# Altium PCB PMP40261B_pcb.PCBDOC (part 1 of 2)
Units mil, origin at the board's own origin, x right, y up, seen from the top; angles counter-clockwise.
Board outline 16142.73 x 9056.12 mil, 2 copper layers (TOP, BOTTOM), stack 10.4 mil thick; 242 components, 121 nets, 575 pads, 103 vias.
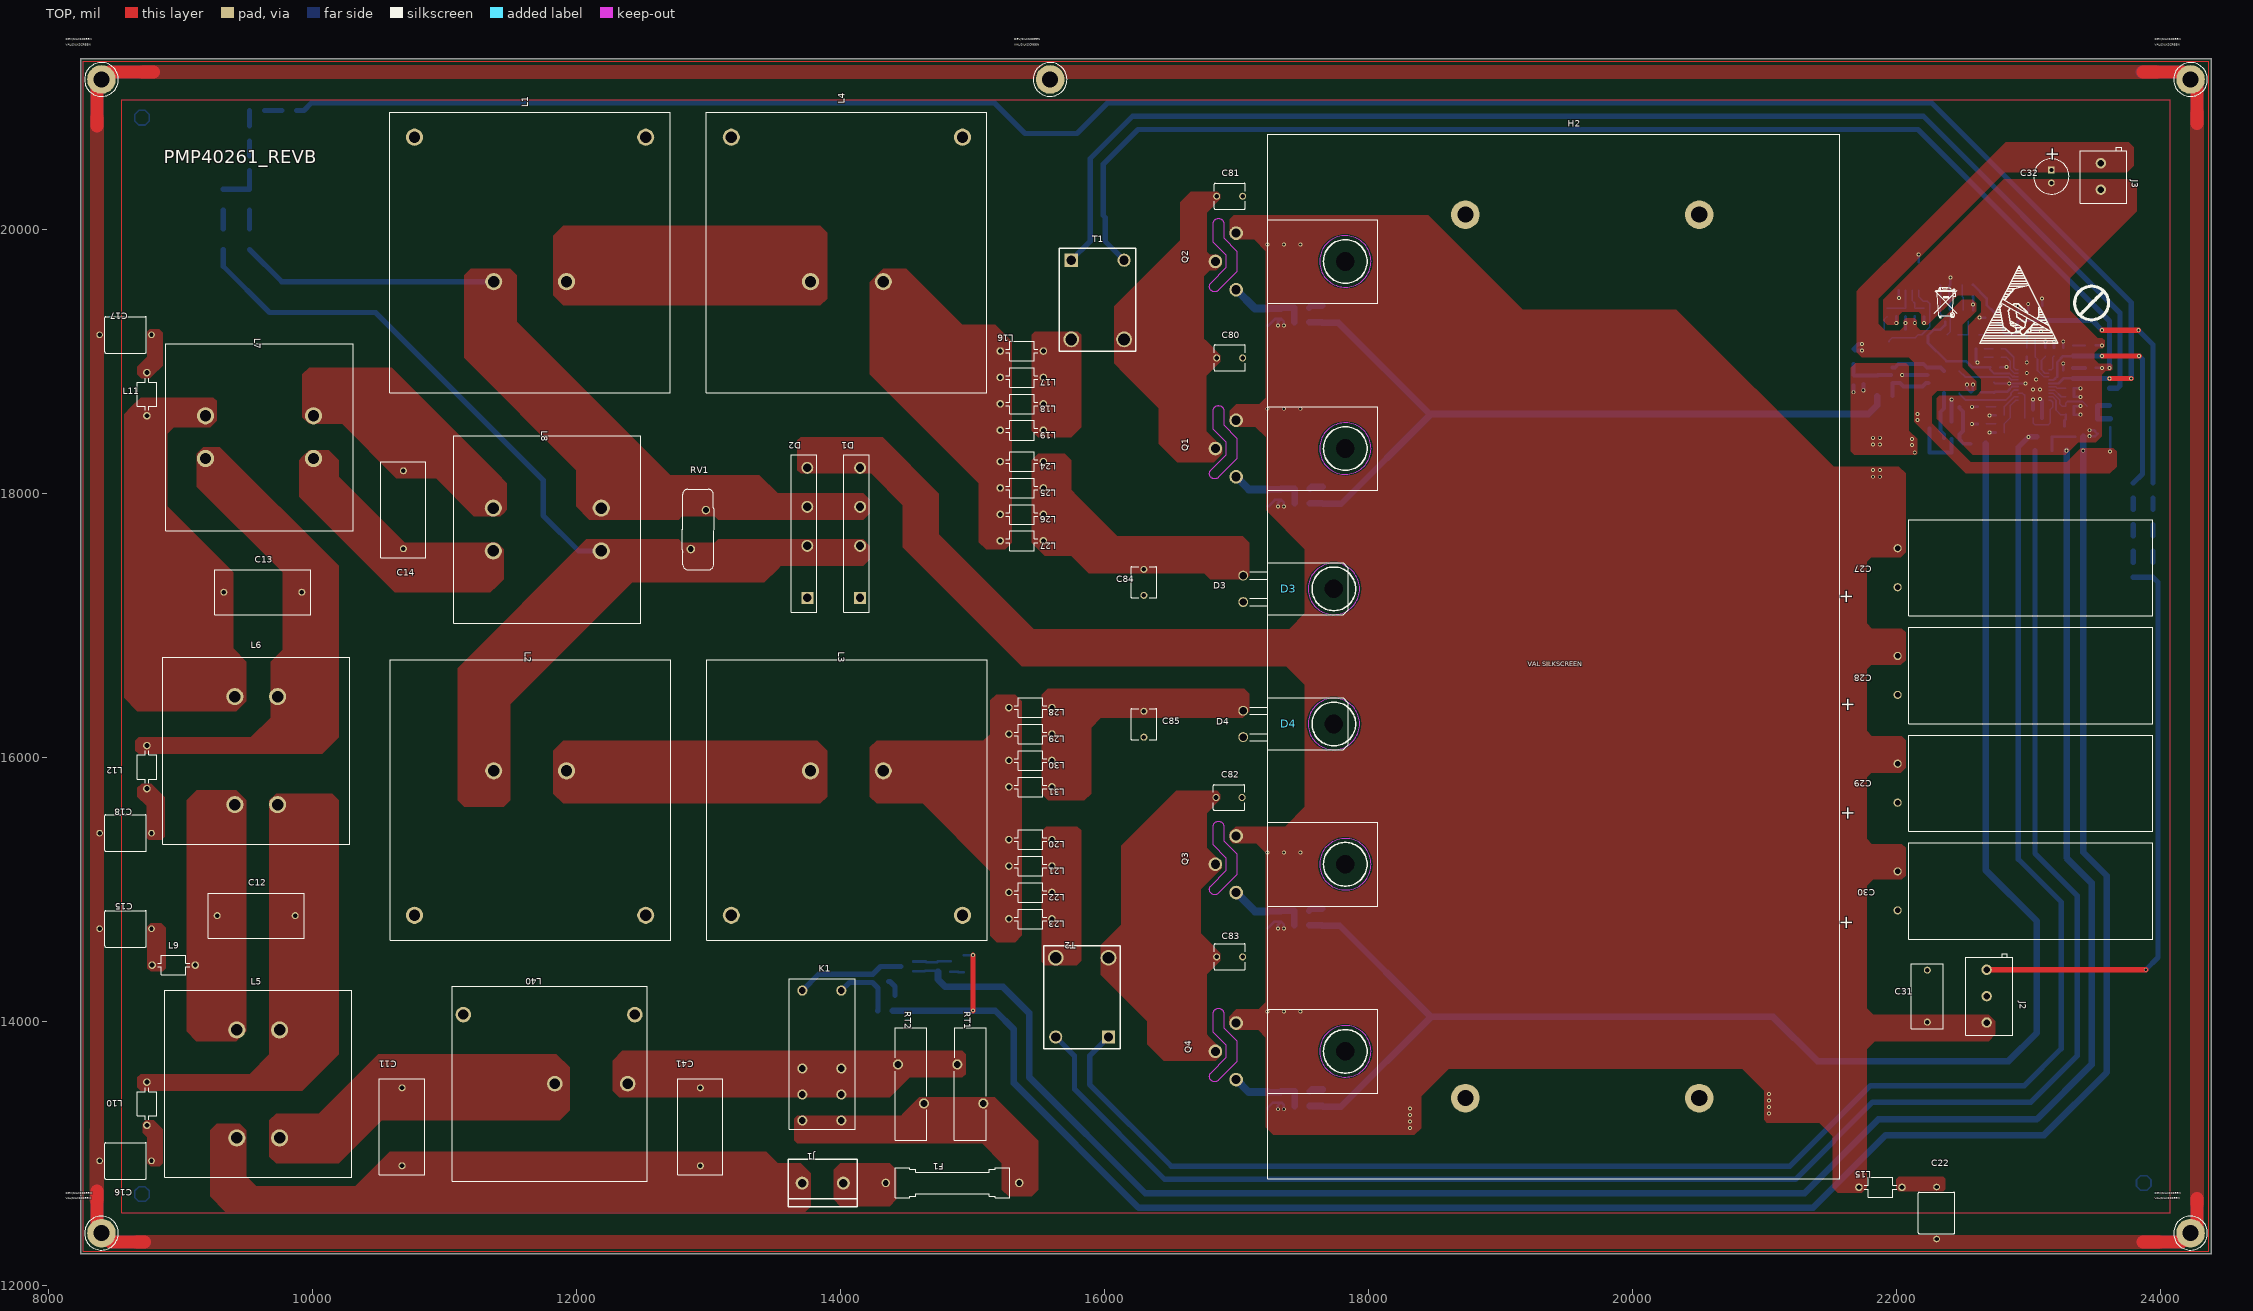
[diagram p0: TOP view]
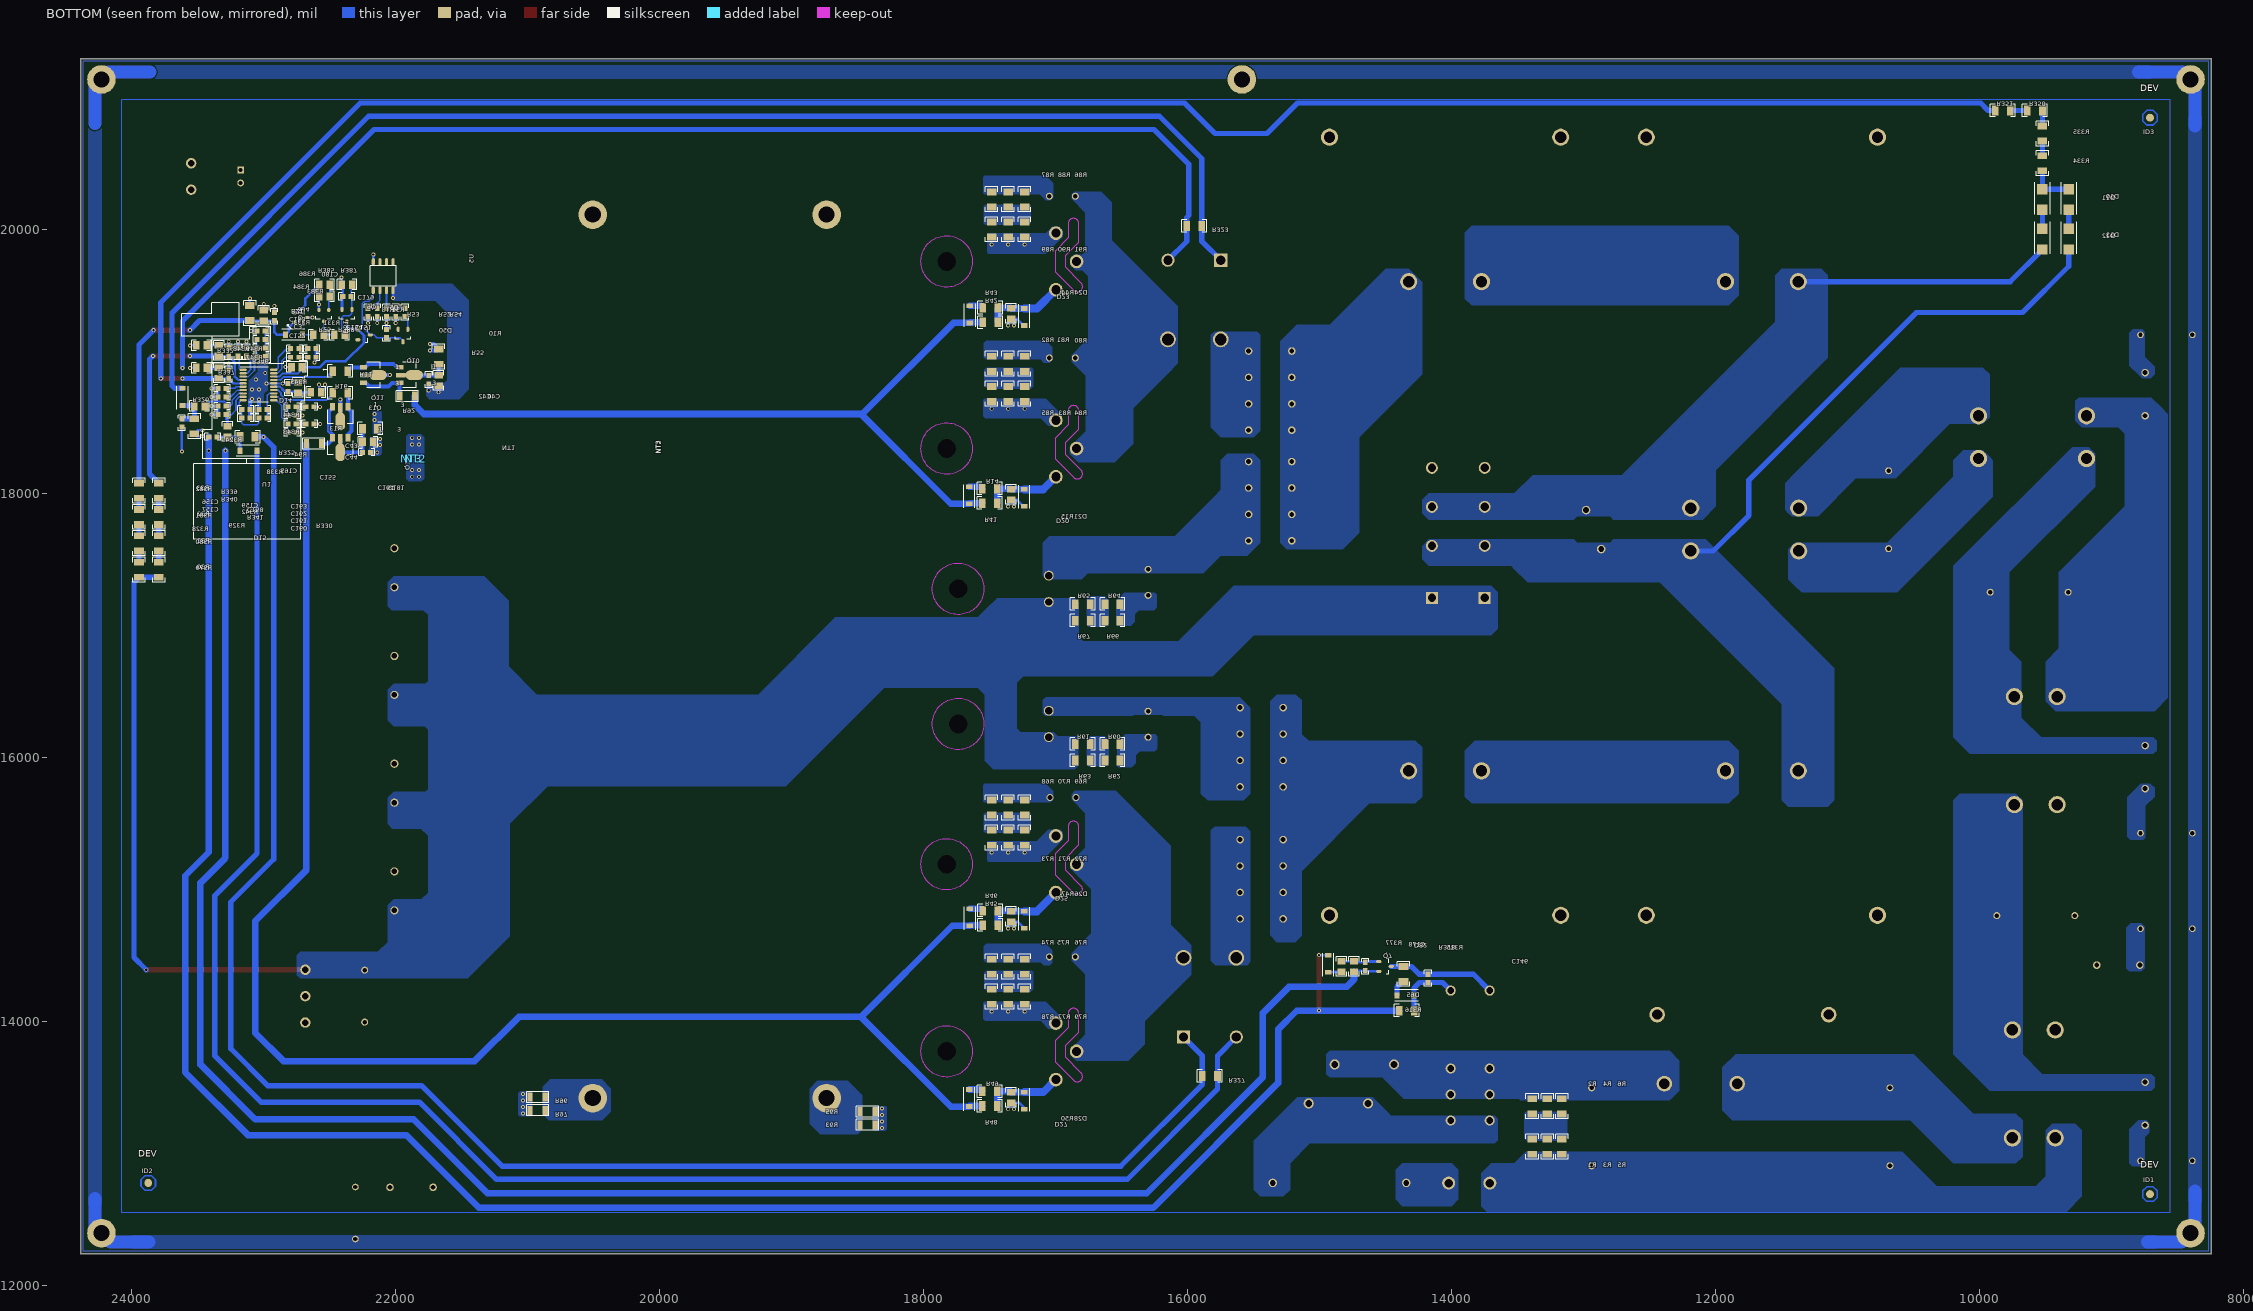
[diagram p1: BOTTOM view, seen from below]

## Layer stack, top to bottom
Top Solder: solder mask 0.4, Solder Resist, Dk 3.5
TOP: signal copper 1.2
Dielectric1: core 8, FR-4, Dk 4.5
BOTTOM: signal copper 1.2
Bottom Solder: solder mask 0.4, Solder Resist, Dk 3.5

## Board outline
8244.65,12237.15 8245.15,12236.65 24386.88,12236.65 24387.38,12237.15 24387.38,21292.27 24386.88,21292.77 8245.15,21292.77 8244.65,21292.27

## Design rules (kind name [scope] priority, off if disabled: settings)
Clearance [All] p1: gap=10 ignorepadtopadclearanceinfootprint=FALSE except(0: Arc-Hole Track-Hole SMDPad-Hole THPad-Hole Via-Hole Fill-Hole Poly-Hole Region-Hole Text-Hole)
FabricationTestPointUsage TestPointUsage [All] p1: valid=0 allowmultiple=FALSE
FabricationTestpoint Testpoint [All] p1: side=3 testpointundercomponent=TRUE minsize=40 maxsize=100 preferedsize=60 minholesize=0 maxholesize=40 preferedholesize=32 testpointgrid=1 allowsidetop=TRUE allowsidebottom=TRUE usegrid=TRUE gridtolerance=0.01
PolygonConnect [All] p1: connectstyle=Direct reliefconductorwidth=10 reliefentries=4 polygonreliefangle="90 Angle" airgapwidth=10
RoutingVias [All] p1: holewidth=28 width=50 viastyle="Through Hole" minholewidth=28 minwidth=50 maxholewidth=28 maxwidth=50
SilkToSolderMaskClearance SilkscreenOverComponentPads [IsPad] p1: minsilkscreentomaskgap=10 clearancetoexposedcopper=TRUE
SolderMaskExpansion [All] p1: expansion=4
Width [All] p1: maxlimit=10 minlimit=10 preferedwidth=10 impedancedriven=TRUE minimp=12.450000 maximp=12.450000 favimp=12.450000
27 further rules are at their usual default settings.

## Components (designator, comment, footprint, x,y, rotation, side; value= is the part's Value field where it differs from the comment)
C3 "0603" 0603 23020,19100 r0 bottom
C11 "KEMET_1800X850X1450" KEMET_1800X850X1450 10680,13200 r90 top
C12 "KEMET_1800X850X1450" KEMET_1800X850X1450 9575,14800 r0 top
C13 "KEMET_1800X850X1450" KEMET_1800X850X1450 9625,17250 r0 top
C14 "KEMET_1800X850X1450" KEMET_1800X850X1450 10690,17875 r270 top
C15 "DE1_87" DE1_87 8585.15,14700 r180 top
C16 "DE1_87" DE1_87 8585.15,12942.15 r180 top
C17 "DE1_87" DE1_87 8585.15,19200 r180 top
C18 "DE1_87" DE1_87 8585.15,15425 r180 top
C22 "DE1_87" DE1_87 22305.15,12547.15 r270 top
C27 "BXW_1800X4500_HORIZONTALDOWN" BXW_1800X4500_HORIZONTALDOWN 22009.8,17435.7 r90 top
C28 "BXW_1800X4500_HORIZONTALDOWN" BXW_1800X4500_HORIZONTALDOWN 22009.8,16619.5 r90 top
C29 "BXW_1800X4500_HORIZONTALDOWN" BXW_1800X4500_HORIZONTALDOWN 22009.8,15803.3 r90 top
C30 "BXW_1800X4500_HORIZONTALDOWN" BXW_1800X4500_HORIZONTALDOWN 22009.8,14987.1 r90 top
C31 "ECWF_L_1250X620X1050" ECWF_L_1250X620X1050 22235,14190 r270 top
C32 "FC_630X1120" FC_630X1120 23175,20400 r270 top
C40 "0805_HV" 0805_HV 21675,18855 r90 bottom
C41 "KEMET_1800X850X1450" KEMET_1800X850X1450 12940,13200 r90 top
C42 "0603" 0603 21750,18860 r90 bottom
C43 "0805_HV" 0805_HV 22211.5,18389.57 r0 bottom
C44 "0603" 0603 22220,18309.57 r0 bottom
C80 "CK45_600X500X1000" CK45_600X500X1000 16950,19025 r0 top
C81 "CK45_600X500X1000" CK45_600X500X1000 16950,20250 r0 top
C82 "CK45_600X500X1000" CK45_600X500X1000 16945,15695 r0 top
C83 "CK45_600X500X1000" CK45_600X500X1000 16950,14487.52 r0 top
C84 "CK45_600X500X1000" CK45_600X500X1000 16300,17325 r270 top
C85 "CK45_600X500X1000" CK45_600X500X1000 16300,16250 r270 top
C146 "0603" 0603 14180,14325 r270 bottom
C151 "0603" 0603 23195,19070 r270 bottom
C152 "0603" 0603 23020,19035 r0 bottom
C153 "0603" 0603 23020,19165 r0 bottom
C154 "0603" 0603 23265,19070 r270 bottom
C155 "0603" 0603 23265,18902 r270 bottom
C156 "0603" 0603 23315,18660 r180 bottom
C157 "0603" 0603 23315,18595 r180 bottom
C158 "0603" 0603 23135,18635 r0 bottom
C159 "0603" 0603 23005,18635 r180 bottom
C160 "0603" 0603 22785,18460 r0 bottom
C161 "0603" 0603 22785,18525 r0 bottom
C162 "0603" 0603 22785,18590 r0 bottom
C163 "0603" 0603 22785,18655 r0 bottom
C164 "0603" 0603 22815,18800 r270 bottom
C165 "0805_HV" 0805_HV 22750,18955 r180 bottom
C178 "0603" 0603 14655,14415 r90 bottom
C179 "0603" 0603 22920,19339.41 r270 bottom
C180 "0603" 0603 22370,19490 r180 bottom
C181 "0805_HV" 0805_HV 22740,18800 r270 bottom
D1 "GBJ" GBJ 14150,17700 r90 top
D2 "GBJ" GBJ 13750,17700 r90 top
D3 "TO-220-2_HORIZ_MH" TO-220-2_HORIZ_MH 17409.73,17275.81 r90 top
D4 "TO-220-2_HORIZ_MH" TO-220-2_HORIZ_MH 17409.73,16252.19 r90 top
D10 "SMA" SMA 9525,20225 r90 bottom
D11 "SMA" SMA 9325,20225 r90 bottom
D12 "SMA" SMA 9325,19925 r90 bottom
D13 "SMA" SMA 9525,19925 r90 bottom
D14 "SOD-123" SOD-123 23615,18730 r270 bottom
D15 "SOD-123" SOD-123 23115,18322.15 r0 bottom
D16 "SOD-123" SOD-123 22770,19200 r0 bottom
D20 "SOD-123" SOD-123 17655,17985 r270 bottom
D21 "SOD-123" SOD-123 17237.8,17965 r90 bottom
D23 "SOD-123" SOD-123 17650,19355 r270 bottom
D24 "SOD-123" SOD-123 17237.8,19335 r90 bottom
D25 "SOD-123" SOD-123 17650,14788.07 r270 bottom
D26 "SOD-123" SOD-123 17237.8,14768.07 r90 bottom
D27 "SOD-123" SOD-123 17655,13418.07 r270 bottom
D28 "SOD-123" SOD-123 17237.8,13398.07 r90 bottom
D50 "SOT-23" SOT-23 21945,19195 r90 bottom
D51 "SOT-23" SOT-23 22240,19200 r0 bottom
D65 "SOD-123" SOD-123 14350,14195 r180 bottom
D82 "SOD-123" SOD-123 14935,14435 r270 bottom
F1 "FUSE_HDP500" FUSE_HDP500 14850,12775 r180 top
H2 "2345-PMP40261" 2345-PMP40261 19405.77,16763.59 r0 top
J1 "AMP_1-1318301-2" AMP_1-1318301-2 13866.99,12774 r180 top
J2 "ON-SHORE_ED120_3DS" ON-SHORE_ED120_3DS 22685,14190 r270 top
J3 "ON-SHORE_ED120_2DS" ON-SHORE_ED120_2DS 23550,20400 r270 top
K1 "RELAY_G2RL-14-E" RELAY_G2RL-14-E 13860,13740 r0 top
L1 "CY0239-AL" CY0239-AL 11650,20150 r90 top
L2 "CY0239-AL" CY0239-AL 11650,15350 r270 top
L3 "CY0239-AL" CY0239-AL 14050,15350 r270 top
L4 "CY0239-AL" CY0239-AL 14050,20150 r90 top
L5 "WURTH_750343785" WURTH_750343785 9590,13525 r0 top
L6 "WURTH_750343684" WURTH_750343684 9575,16050 r0 top
L7 "WURTH_750343785" WURTH_750343785 9600,18425 r270 top
L8 "WURTH_750343684" WURTH_750343684 11780,17725 r270 top
L9 "28L0138" 28L0138 8950,14425 r0 top
L10 "28L0138" 28L0138 8746.85,13375 r90 top
L11 "28L0138" 28L0138 8746.85,18750 r270 top
L12 "28L0138" 28L0138 8746.85,15925 r90 top
L15 "28L0138" 28L0138 21880.15,12742.15 r180 top
L16 "28L0138" 28L0138 15375,19077.26 r180 top
L17 "28L0138" 28L0138 15375,18877.26 r180 top
L18 "28L0138" 28L0138 15375,18677.26 r180 top
L19 "28L0138" 28L0138 15375,18477.26 r180 top
L20 "28L0138" 28L0138 15440,15375.74 r180 top
L21 "28L0138" 28L0138 15440,15175.74 r180 top
L22 "28L0138" 28L0138 15440,14975.74 r180 top
L23 "28L0138" 28L0138 15440,14775.74 r180 top
L24 "28L0138" 28L0138 15375,18240 r180 top
L25 "28L0138" 28L0138 15375,18040 r180 top
L26 "28L0138" 28L0138 15375,17840 r180 top
L27 "28L0138" 28L0138 15375,17640 r180 top
L28 "28L0138" 28L0138 15440,16375.74 r180 top
L29 "28L0138" 28L0138 15440,16175.74 r180 top
L30 "28L0138" 28L0138 15440,15975.74 r180 top
L31 "28L0138" 28L0138 15440,15775.74 r180 top
L40 "CY0203-BL" CY0203-BL 11794.09,13788.78 r180 top
NT1 "NET-TIE_10MIL" NET-TIE_10MIL 21820,18260 r270 bottom
NT2 "NET-TIE_10MIL" NET-TIE_10MIL 21850,18260 r270 bottom
NT3 "NET-TIE_10MIL" NET-TIE_10MIL 21880,18260 r270 bottom
Q1 "TO-247_HORIZONTAL_DOWN_1" TO-247_HORIZONTAL_DOWN_1 17340.58,18338.8 r90 top
Q2 "TO-247_HORIZONTAL_DOWN_1" TO-247_HORIZONTAL_DOWN_1 17340.58,19756.13 r90 top
Q3 "TO-247_HORIZONTAL_DOWN_1" TO-247_HORIZONTAL_DOWN_1 17340.58,15189.2 r90 top
Q4 "TO-247_HORIZONTAL_DOWN_1" TO-247_HORIZONTAL_DOWN_1 17340.58,13771.87 r90 top
Q5 "SOT-23" SOT-23 22370,19345 r90 bottom
Q6 "SOT-23L" SOT-23L 22545,19345 r90 bottom
Q7 "SOT-23" SOT-23 14505,14415 r0 bottom
Q10 "SOT-89-3" SOT-89-3 21895,18895 r0 bottom
Q11 "SOT-89-3" SOT-89-3 22170,18895 r0 bottom
Q12 "SOT-89-3" SOT-89-3 22420,18345 r90 bottom
Q13 "SOT-89-3" SOT-89-3 22420,18580 r90 bottom
R1 "1206" 1206 13390,13050 r90 bottom
R2 "1206" 1206 13390,13355 r90 bottom
R3 "1206" 1206 13275,13050 r90 bottom
R4 "1206" 1206 13275,13355 r90 bottom
R5 "1206" 1206 13165,13050 r90 bottom
R6 "1206" 1206 13165,13355 r90 bottom
R10 "1206" 1206 21675,19035 r90 bottom
R11 "1206" 1206 22420,18925 r0 bottom
R13 "1206" 1206 22194.41,18489.57 r180 bottom
R14 "1206" 1206 17500,18035 r0 bottom
R15 "0805_HV" 0805_HV 17337.8,17990 r90 bottom
R16 "1206" 1206 22420,18760 r0 bottom
R21 "0603" 0603 23020,19230 r0 bottom
R25 "0805_HV" 0805_HV 22585,19200 r0 bottom
R30 "1206" 1206 23795,17420 r90 bottom
R31 "1206" 1206 23795,17620 r90 bottom
R32 "1206" 1206 23795,17820 r90 bottom
R33 "1206" 1206 23795,18020 r90 bottom
R41 "1206" 1206 17500,17925 r0 bottom
R42 "1206" 1206 17495,19295 r0 bottom
R43 "1206" 1206 17495,19405 r0 bottom
R44 "0805_HV" 0805_HV 17337.8,19360 r90 bottom
R45 "1206" 1206 17495,14728.07 r0 bottom
R46 "1206" 1206 17495,14838.07 r0 bottom
R47 "0805_HV" 0805_HV 17337.8,14793.07 r90 bottom
R48 "1206" 1206 17500,13358.07 r0 bottom
R49 "1206" 1206 17500,13468.07 r0 bottom
R50 "0805_HV" 0805_HV 17337.8,13423.07 r90 bottom
R51 "0603" 0603 22070,19370 r90 bottom
R52 "0603" 0603 22000,19370 r270 bottom
R53 "0603" 0603 22210,19370 r270 bottom
R54 "0603" 0603 21930,19370 r270 bottom
R55 "0603" 0603 22070,19210 r270 bottom
R60 "1206" 1206 16570,16100 r0 bottom
R61 "1206" 1206 16795,16100 r0 bottom
R62 "1206" 1206 16570,15975 r0 bottom
R63 "1206" 1206 16795,15975 r0 bottom
R64 "1206" 1206 16570,17160 r0 bottom
R65 "1206" 1206 16795,17160 r0 bottom
R66 "1206" 1206 16570,17035 r0 bottom
R67 "1206" 1206 16795,17035 r0 bottom
R68 "1206" 1206 17485,15618.86 r90 bottom
R69 "1206" 1206 17235,15618.86 r90 bottom
R70 "1206" 1206 17360,15618.86 r90 bottom
R71 "1206" 1206 17360,15391.06 r90 bottom
R72 "1206" 1206 17235,15391.06 r90 bottom
R73 "1206" 1206 17485,15391.06 r90 bottom
R74 "1206" 1206 17485,14413.07 r90 bottom
R75 "1206" 1206 17360,14413.07 r90 bottom
R76 "1206" 1206 17235,14413.07 r90 bottom
R77 "1206" 1206 17360,14185.27 r90 bottom
R78 "1206" 1206 17485,14185.27 r90 bottom
R79 "1206" 1206 17235,14185.27 r90 bottom
R80 "1206" 1206 17235,18980 r90 bottom
R81 "1206" 1206 17360,18980 r90 bottom
R82 "1206" 1206 17485,18980 r90 bottom
R83 "1206" 1206 17360,18752.2 r90 bottom
R84 "1206" 1206 17235,18752.2 r90 bottom
R85 "1206" 1206 17485,18752.2 r90 bottom
R86 "1206" 1206 17235,20225.79 r90 bottom
R87 "1206" 1206 17485,20225.79 r90 bottom
R88 "1206" 1206 17360,20225.79 r90 bottom
R89 "1206" 1206 17485,19997.99 r90 bottom
R90 "1206" 1206 17360,19997.99 r90 bottom
R91 "1206" 1206 17235,19997.99 r90 bottom
R92 "5108" 5108 21912.13,18735.04 r0 bottom
R93 "5108" 5108 18425.87,13214.96 r180 bottom
R94 "5108" 5108 22620.87,18374.96 r180 bottom
R95 "5108" 5108 18425.87,13314.96 r180 bottom
R96 "5108" 5108 20924.13,13425.04 r0 bottom
R97 "5108" 5108 20924.13,13325.04 r0 bottom
R315 "1206" 1206 14365,14357.91 r90 bottom
R316 "1206" 1206 14340,14080 r180 bottom
R323 "1206" 1206 15950,20025 r0 bottom
R324 "0603" 0603 23620.15,18532.74 r90 bottom
R325 "1206" 1206 23525.15,18507.15 r270 bottom
R326 "0805_HV" 0805_HV 23485,18660 r0 bottom
R327 "1206" 1206 15831.89,13585.28 r0 bottom
R328 "0603" 0603 23385.15,18427.15 r180 bottom
R329 "1206" 1206 23122.38,18427.15 r180 bottom
R330 "0805_HV" 0805_HV 23275,18467.15 r270 bottom
R331 "0603" 0603 23130,19070 r90 bottom
R332 "0805_HV" 0805_HV 23470,19120 r0 bottom
R333 "0805_HV" 0805_HV 23340,19080 r90 bottom
R334 "1206" 1206 9525,20500 r90 bottom
R335 "1206" 1206 9525,20725 r90 bottom
R337 "0805_HV" 0805_HV 23470,18950 r0 bottom
R338 "0805_HV" 0805_HV 23340,18910 r90 bottom
R339 "0603" 0603 23315,18795 r0 bottom
R340 "0603" 0603 23315,18730 r0 bottom
R341 "0603" 0603 23135,18570 r0 bottom
R342 "0603" 0603 23005,18570 r180 bottom
R343 "0603" 0603 22650,18525 r180 bottom
R344 "0603" 0603 22650,18655 r180 bottom
R345 "0805_HV" 0805_HV 22605,18765 r180 bottom
R346 "0603" 0603 22765,19030 r0 bottom
R347 "0603" 0603 22635,19030 r180 bottom
R348 "0603" 0603 22765,19095 r180 bottom
R349 "0603" 0603 22635,19095 r180 bottom
R350 "1206" 1206 9582.09,20900 r0 bottom
R351 "1206" 1206 9825,20900 r0 bottom
R377 "0805_HV" 0805_HV 14835,14415 r90 bottom
R378 "0805_HV" 0805_HV 14740,14415 r270 bottom
R379 "1206" 1206 23945,17420 r90 bottom
R380 "1206" 1206 23945,17620 r90 bottom
R381 "1206" 1206 23945,17820 r90 bottom
R382 "1206" 1206 23945,18020 r90 bottom
R383 "0805_HV" 0805_HV 23000,19347.91 r90 bottom
R384 "1206" 1206 23105,19365 r90 bottom
R385 "0805_HV" 0805_HV 22540,19580 r0 bottom
R386 "0805_HV" 0805_HV 22540,19490 r180 bottom
R387 "0805_HV" 0805_HV 22370,19580 r0 bottom
R388 "0805_HV" 0805_HV 22425,19200 r0 bottom
RT1 "SCK20_S" SCK20_S 14985,13525 r180 top
RT2 "SCK20_S" SCK20_S 14535,13525 r180 top
RT3 "0603" 0603 22140,19370 r90 bottom
RV1 "TDK_B72214S0421" TDK_B72214S0421 12925,17725 r270 top
T1 "XFMR_CS4200V-01L" XFMR_CS4200V-01L 15950,19460.57 r0 top
T2 "XFMR_CS4200V-01L" XFMR_CS4200V-01L 15831.89,14185.54 r180 top
U1 "PW0020A_N" PW0020A_N 23040,18819.99 r0 bottom
U4 "DBZ0003A_N" DBZ0003A_N 22720,19330 r0 bottom
U5 "D0008A_N" D0008A_N 22095,19645 r270 bottom

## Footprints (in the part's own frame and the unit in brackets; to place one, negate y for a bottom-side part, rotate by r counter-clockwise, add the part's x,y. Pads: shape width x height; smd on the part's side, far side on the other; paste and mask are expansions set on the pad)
28L0138 [mil] "28L0138"
  round 57.09 hole 37.4: 1(-163.19,0) 2(163.19,0)
  silkscreen extent -122,-74 122,74
0603 [mil] "0603"
  rect 39.37x37.4 smd: 1(31.5,0) 2(-31.5,0)
  silkscreen extent -60,-27 60,27
0805_HV [mil] "0805_HV"
  rect 50x63 smd: 1(40,0) 2(-40,0)
  silkscreen extent -74,-40 74,40
1206 [mil] "1206"
  rect 51.18x72.83 smd: 1(57.09,0) 2(-57.09,0)
  silkscreen extent -94,-48 94,48
2345-PMP40261 [mil] "2345-PMP40261"
  round 216.53 hole 122.05: 1(-670.26,3346.87) 2(1101.39,3346.87) 3(-670.26,-3346.05) 4(1101.39,-3346.05)
  silkscreen extent -2166,-3956 2164,3957
5108 [mm] "5108"
  rect 1.01x1.73 smd: 1(1.467,0.001) 2(-1.423,0.001)
  silkscreen extent -2.14,-1.06 2.14,1.06
AMP_1-1318301-2 [mm] "AMP_1-1318301-2"
  round 2.5 hole 1.65: 1(-3.96,0) 2(3.96,0)
  silkscreen extent -6.6,-4.57 6.6,4.57
BXW_1800X4500_HORIZONTALDOWN [mil] "BXW_1800X4500_HORIZONTALDOWN"
  round 62.01 hole 41.34: 1(-147.64,0) 2(147.64,0)
  silkscreen extent -364,-1935 364,-85
CK45_600X500X1000 [mm] "CK45_600X500X1000"
  round 1.35 hole 0.9: 1(-2.5,0) 2(2.5,0)
  silkscreen extent -3,-2.5 3,2.5
CY0203-BL [mm] "CY0203-BL"
  round 3 hole 2: 1(-15.1,6.65) 2(-1.1,6.65) 3(16.5,-6.65) 4(-16.5,-6.65)
  silkscreen extent -19.25,-12.05 18.6,25.45
CY0239-AL [mm] "CY0239-AL"
  round 3.3 hole 2.2: 1(-13.9,7) 2(-13.9,-7) 3(13.9,-22.25) 4(13.9,22.25)
  silkscreen extent -35.3,-26.95 18.7,27.4
D0008A_N [mil] "D0008A_N"
  oval 57.09x23.62 smd: 1(107.28,-75) 2(107.28,-25) 3(107.28,25) 4(107.28,75) 5(-107.28,75) 6(-107.28,25) 7(-107.28,-25) 8(-107.28,-75)
  silkscreen extent -79,-98 172,98
DBZ0003A_N [mm] "DBZ0003A_N"
  oval 1x0.6 smd: 1(1.2,-0.95) 2(1.2,0.95) 3(-1.2,0)
  silkscreen extent -0.7,-1.5 1.65,1.5
DE1_87 [mm] "DE1_87"
  round 1.275 hole 0.85: 1(-5,0) 2(5,0)
  silkscreen extent -4,-3.5 4,3.5
ECWF_L_1250X620X1050 [mm] "ECWF_L_1250X620X1050"
  round 1.35 hole 0.85: 1(-5,0) 2(5,0)
  silkscreen extent -6.25,-3.1 6.25,3.1
FC_630X1120 [mil] "FC_630X1120"
  rect 51.18x51.18 hole 31.5: 1(-49.21,0)
  round 51.18 hole 31.5: 2(49.21,0)
  silkscreen extent -134,-134 134,134
FUSE_HDP500 [mm] "FUSE_HDP500"
  round 1.65 hole 1.1: 1(-12.84,0) 2(12.84,0)
  silkscreen extent -11,-2.9 11,2.9
GBJ [mm] "GBJ"
  rect 2.3x2.3 hole 1.6: 1(-12.5,0)
  round 2.3 hole 1.6: 2(-2.5,0) 3(5,0) 4(12.5,0)
  silkscreen extent -15.3,-1.8 15,3.1
KEMET_1800X850X1450 [mm] "KEMET_1800X850X1450"
  round 1.35 hole 0.9: 1(-7.5,0) 2(7.5,0)
  silkscreen extent -9.25,-4.35 9.25,4.35
NET-TIE_10MIL [mil] "NET-TIE_10MIL"
  rect 10x10 smd: 1(10,0) 2(-10,0)
ON-SHORE_ED120_2DS [mm] "ON-SHORE_ED120_2DS"
  round 2 hole 1.25: 1(-2.54,0) 2(2.54,0)
  silkscreen extent -5.6,-4 5.12,5
ON-SHORE_ED120_3DS [mm] "ON-SHORE_ED120_3DS"
  round 2 hole 1.25: 1(-5.08,0) 2(0,0) 3(5.08,0)
  silkscreen extent -8.14,-4 7.5,5
PW0020A_N [mil] "PW0020A_N"
  oval 55.12x17.72 smd: 1(116.14,-115.17) 2(116.14,-89.58) 3(116.14,-63.99) 4(116.14,-38.4) 5(116.14,-12.8) 6(116.14,12.78) 7(116.14,38.38) 8(116.14,63.97) 9(116.14,89.56) 10(116.14,115.15) 11(-116.14,115.15) 12(-116.14,89.56) 13(-116.14,63.97) 14(-116.14,38.38) 15(-116.14,12.78) 16(-116.14,-12.8) 17(-116.14,-38.4) 18(-116.14,-63.99) 19(-116.14,-89.58) 20(-116.14,-115.17)
  silkscreen extent -73,-134 138,130
RELAY_G2RL-14-E [mil] "RELAY_G2RL-14-E"
  round 76.77 hole 51.18: 1(-147.64,492.13) 2(-147.64,-98.42) 3(-147.64,-295.28) 4(-147.64,-492.13) 5(147.64,-492.13) 6(147.64,-295.28) 7(147.64,-98.42) 8(147.64,492.13)
  silkscreen extent -260,-559 254,583
SCK20_S [mil] "SCK20_S"
  round 76.77 hole 51.18: 1(-98.42,147.64) 2(98.42,-147.64)
  silkscreen extent -120,-425 120,425
SMA [mm] "SMA"
  rect 2x2 smd: 1(2,0) 2(-2,0)
  silkscreen extent -2.79,-1.57 3.66,1.57
SOD-123 [mil] "SOD-123"
  rect 36.02x48.03 smd: 1(64.47,0) 2(-64.47,0)
  silkscreen extent -80,-46 108,46
SOT-23 [mm] "SOT-23"
  oval 1x0.6 smd: 1(1.2,-0.95) 2(1.2,0.95) 3(-1.2,0)
  silkscreen extent -0.7,-1.5 1.63,1.5
SOT-23L [mil] "SOT-23L"
  oval 31.5x23.62 smd: 1(43.31,-37.4) 2(43.31,37.4) 3(-43.31,0)
  silkscreen extent -28,-59 59,59
SOT-89-3 [mil] "SOT-89-3"
  rect 55.12x35.43 smd: 1(74.8,-59.05) 3(74.8,59.05)
  rect 70.87x35.43 smd: 2(66.93,0)
  oval 133.86x74.8 smd: 4(-35.43,0)
  silkscreen extent -52,-96 51,96
TDK_B72214S0421 [mm] "TDK_B72214S0421"
  round 1.65 hole 1.1: 1(-3.75,1.45) 2(3.75,-1.45)
  silkscreen extent -7.75,-3.13 7.75,3.05
TO-220-2_HORIZ_MH [mil] "TO-220-2_HORIZ_MH"
  round 74.8 hole 55.12: 1(-100,357.29) 2(100,357.29)
  round 129.92 hole 141.73: MH(0,-329.72)
  silkscreen extent -197,-440 197,306
TO-247_HORIZONTAL_DOWN_1 [mil] "TO-247_HORIZONTAL_DOWN_1"
  round 103.35 hole 68.9: 1(-214.17,341.29) 2(0,498.77) 3(214.17,341.29)
  round 129.92 hole 141.73: MH-1(0,-485.48)
  silkscreen extent -319,-730 318,125
WURTH_750343684 [mil] "WURTH_750343684"
  round 129.92 hole 86.61: 1(-162.01,409.05) 2(-162.01,-409.05) 3(162.01,-409.05) 4(162.01,409.05)
  silkscreen extent -709,-709 709,744
WURTH_750343785 [mil] "WURTH_750343785"
  round 129.92 hole 86.61: 1(-162.01,409.05) 2(-162.01,-409.05) 3(162.01,-409.05) 4(162.01,409.05)
  silkscreen extent -732,-709 709,709
XFMR_CS4200V-01L [mil] "XFMR_CS4200V-01L"
  rect 100x100 hole 70: 1(-200,305)
  round 120 hole 89: 2(-200,-295) 3(200,-295)
  round 100 hole 70: 4(200,305)
  silkscreen extent -290,-385 290,395

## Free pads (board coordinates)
  round 216.53 hole 122.05: 1(8402.63,12394.63) 1(8402.63,21134.79) 1(15589.4,21134.79) 1(24229.4,12394.63) 1(24229.4,21134.79)
  round 60 smd far side: 1(8710,12690) 1(8710,20845) 1(23875,12775)

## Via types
v1: diameter 30, hole 16, TOP to BOTTOM, 103 vias

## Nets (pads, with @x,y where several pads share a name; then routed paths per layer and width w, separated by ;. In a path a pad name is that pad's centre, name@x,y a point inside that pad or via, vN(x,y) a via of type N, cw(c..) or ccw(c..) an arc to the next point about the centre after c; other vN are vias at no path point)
CASE: C15.2 C16.2 C17.2 C18.2 C22.2 | length 5008.8
  TOP w100: 8368.3,12711.79 8368.3,12428.96 8470.11,12327.15 8729.64,12327.15 ; 8368.3,20783.28 8368.3,21100.46 8458.69,21190.85 8794.94,21190.85 ; 23871.32,12327.15 24161.92,12327.15 24278.85,12444.08 24278.85,12575 24278.85,12656.41 ; 23871.32,21190.85 24173.34,21190.85 24229.4,21134.79 24230.21,21134.79 24278.85,21086.15 24278.85,20800
  BOTTOM w100: 8368.3,12711.79 8368.3,12428.96 8470.11,12327.15 8729.64,12327.15 ; 8368.3,20783.28 8368.3,21100.46 8458.69,21190.85 8794.94,21190.85 ; 23871.32,12327.15 24161.92,12327.15 24278.85,12444.08 24278.85,12656.41
CS_A: C157.1 R330.2 U1.9 | length 318.8
  BOTTOM w12: U1.9@23156.14,18730.43 23184.57,18730.43 23210,18705 23210,18649.69 23210.19,18649.5 23210.19,18629.81 23245,18595 C157.1@23283.5,18595
  BOTTOM w20: R330.2@23275,18507.15 23275,18553.65 23283.5,18562.15 C157.1@23283.5,18595
CS_B: C156.1 R326.2 U1.8 | length 389.1
  BOTTOM w12: U1.8@23156.14,18756.02 23188.98,18756.02 23240,18705 23240,18674.81 23254.81,18660 C156.1@23283.5,18660 23283.5,18683.5 23295,18695 23410,18695 R326.2@23445,18660
GD_A: R16.1 U1.14 | length 514.2
  BOTTOM w15: R16.1@22477.09,18760 22477.09,18752.92 22525.01,18705 22830,18705 22870,18745 22870,18760 22891.61,18781.61 U1.14@22923.86,18781.61
GD_B: R11.1 U1.17 | length 474.4
  BOTTOM w12: 22871.61,18858.39 U1.17@22923.86,18858.39
  BOTTOM w15: R11.1@22477.09,18925 22521.09,18881 22849,18881 22871.61,18858.39
GDA_1: D25.1 D27.1 R45.1 R48.1 R94.2 | length 11853.6
  BOTTOM w50: R45.1@17552.09,14728.07 17645.53,14728.07 D25.1@17650,14723.6 17784.47,14723.6 18475,14033.07 ; R48.1@17557.09,13358.07 17650.53,13358.07 D27.1@17655,13353.6 17795.53,13353.6 18475,14033.07 ; R94.2@22676.89,18375 22676.89,15145.41 23065,14757.3 23065,13912 22850.52,13697.52 21402.48,13697.52 21066.93,14033.07 18475,14033.07
GDB_1: D20.1 D23.1 R41.1 R42.1 R92.2 | length 5888.3
  BOTTOM w50: R42.1@17552.09,19295 17645.53,19295 D23.1@17650,19290.53 17774.47,19290.53 18465,18600 18475,18600 ; R41.1@17557.09,17925 17650.53,17925 D20.1@17655,17920.53 17795.53,17920.53 18475,18600 ; R92.2@21856.11,18735 21856.11,18667.94 21788.17,18600 18475,18600
HV_DC: C27.1 C28.1 C29.1 C30.1 C31.1 D1.1 D2.1 D3.1 D4.1 J2.1 R30.2 R61.1 R63.1 R65.1 R67.1 R379.2 | length 4381.4
  TOP w40: J2.1@22685,14390 v1(23890,14390)
  BOTTOM w40: R30.2@23795,17362.91 R379.2@23945,17362.91 23982.09,17325.82 23982.09,14482.09 v1(23890,14390)
K1_COIL_1: C146.1 D65.1 K1.8 R316.1 | length 493.5
  BOTTOM w40: K1.8@14007.64,14232.13 14069.01,14293.5 C146.1@14180,14293.5 14243.93,14293.5 14285.53,14251.9 D65.1@14285.53,14195 14285.53,14082.62 R316.1@14282.91,14080
K1_COIL_2: C146.2 K1.1 Q7.3 R315.1 | length 821.1
  BOTTOM w40: K1.1@13712.36,14232.13 13836.73,14356.5 C146.2@14180,14356.5 14246.49,14356.5 14304.99,14415 R315.1@14365,14415 Q7.3@14457.76,14415
NETC3_1: C3.1 C152.1 C153.1 U1.3 | length 347.9
  BOTTOM w12: C153.1@23051.5,19165 C3.1@23051.5,19100 C152.1@23051.5,19035 23070,19016.5 23070,18930 23116.02,18883.98 U1.3@23156.14,18883.98
NETC3_2: C3.2 C153.2 R21.2 | length 130
  BOTTOM w12: C3.2@22988.5,19100 C153.2@22988.5,19165 R21.2@22988.5,19230
NETC11_1: C11.1 C41.1 J1.2 L5.2 R1.2 R3.2 R5.2
NETC11_2: C11.2 L5.3 L40.2
NETC12_1: C12.1 L5.1 L6.2 L9.2
NETC12_2: C12.2 L5.4 L6.3 L10.2
NETC13_1: C13.1 L6.1 L7.2 L11.2
NETC13_2: C13.2 L6.4 L7.3 L12.2
NETC14_1: C14.1 L7.1 L8.2
NETC14_2: C14.2 L7.4 L8.3
NETC15_1: C15.1 L9.1
NETC16_1: C16.1 L10.1
NETC17_1: C17.1 L11.1
NETC18_1: C18.1 L12.1
NETC22_1: C22.1 L15.1
NETC40_1: C40.1 C42.1 Q10.2 Q10.4 R10.2 | length 372.7
  BOTTOM w30: R10.2@21675,18977.91 C40.1@21675,18895 21678.5,18891.5 C42.1@21750,18891.5 21856.07,18891.5 Q10.4@21859.57,18895 Q10.2@21961.93,18895
NETC41_2: C41.2 K1.2 K1.3 K1.6 K1.7 L40.1 R2.1 R4.1 R6.1 RT1.2 RT2.2
NETC43_1: C43.1 C44.1 Q12.2 Q12.4 R13.2 | length 450.9
  BOTTOM w30: R13.2@22251.5,18489.57 C43.1@22251.5,18389.57 C44.1@22251.5,18309.57 Q12.4@22420,18309.57 Q12.2@22420,18411.93
NETC80_1: C80.1 C81.1 Q1.2 Q2.2 T1.3
NETC80_2: C80.2 R80.1 R81.1 R82.1
NETC81_2: C81.2 R86.1 R87.1 R88.1
NETC82_1: C82.1 C83.1 Q3.2 Q4.2 T2.2
NETC82_2: C82.2 R68.1 R69.1 R70.1
NETC83_2: C83.2 R74.1 R75.1 R76.1
NETC84_1: C84.1 D3.2 L24.1 L25.1 L26.1 L27.1
NETC84_2: C84.2 R64.2 R66.2
NETC85_1: C85.1 D4.2 L28.1 L29.1 L30.1 L31.1
NETC85_2: C85.2 R60.2 R62.2
NETC151_1: C151.1 U1.1 | length 130.6
  BOTTOM w12: U1.1@23156.14,18935.16 23175.16,18935.16 23185,18945 23185,19028.5 C151.1@23195,19038.5
NETC158_1: C158.1 R341.1 R342.2 U1.10 | length 377.7
  BOTTOM w12: R342.2@23036.5,18570 23036.5,18533.5 23050,18520 23154.5,18520 23166.5,18532 R341.1@23166.5,18570 C158.1@23166.5,18635 23185,18653.5 23185,18690 23170.16,18704.84 U1.10@23156.14,18704.84
NETC160_1: C160.1 C161.1 U1.11 | length 300.5
  BOTTOM w12: C160.1@22816.5,18460 C161.1@22816.5,18525 22865,18573.5 22865,18665 22904.84,18704.84 U1.11@22923.86,18704.84
NETC161_2: C161.2 R343.2 | length 72
  BOTTOM w12: R343.2@22681.5,18525 C161.2@22753.5,18525
NETC162_1: C162.1 C163.1 U1.12 | length 203.6
  BOTTOM w12: C162.1@22816.5,18590 C163.1@22816.5,18655 22817.49,18655 22892.92,18730.43 U1.12@22923.86,18730.43
NETC163_2: C163.2 R344.2 | length 72
  BOTTOM w12: R344.2@22681.5,18655 C163.2@22753.5,18655
NETC164_1: C164.1 C181.1 R345.2 U1.15 | length 300.5
  BOTTOM w15: 22859.99,18789.99 22877.21,18807.21 U1.15@22923.86,18807.21
  BOTTOM w20: R345.2@22645,18765 22735,18765 C181.1@22740,18760 22748.5,18768.5 C164.1@22815,18768.5 22838.5,18768.5 22859.99,18789.99
NETC178_1: C178.1 Q7.1 R377.1 R378.2 | length 288.7
  BOTTOM w20: Q7.1@14552.24,14452.4 14649.1,14452.4 C178.1@14655,14446.5 14731.5,14446.5 R378.2@14740,14455 R377.1@14835,14455
NETC179_1: C179.1 D16.1 R382.1 R383.2 R384.2 U4.2 | length 2453.9
  TOP w40: v1(23560,19235) v1(23835,19235)
  BOTTOM w20: U4.2@22767.24,19292.6 22772.4,19292.6 22810,19255 22810,19224.47 D16.1@22834.47,19200 22900,19200 22920,19220 C179.1@22920,19307.91 R383.2@23000,19307.91 R384.2@23105,19307.91
  BOTTOM w40: R384.2@23105,19307.91 23487.09,19307.91 v1(23560,19235) ; v1(23835,19235) 23945,19125 R382.1@23945,18077.09
NETC180_1: C180.1 Q5.1 R387.2 R388.2 | length 454.7
  BOTTOM w12: R387.2@22330,19580 22338.5,19571.5 C180.1@22338.5,19490 22332.6,19484.1 Q5.1@22332.6,19392.24 22332.6,19362.4 22350,19345 22395,19345 22410,19330 22410,19225 R388.2@22385,19200
NETD1_2: D1.2 D2.2 D12.2 L2.2 L8.4 RV1.2 | length 4041.2
  BOTTOM w40: D12.2@9325,19846.26 9325,19720 9675,19370 10480,19370 11749.02,18100.98 11749.02,17832.22 12018.25,17562.99 L8.4@12189.05,17562.99
NETD10_1: D10.1 D11.1 R334.2 | length 339.2
  BOTTOM w40: D11.1@9325,20303.74 D10.1@9525,20303.74 R334.2@9525,20442.91
NETD10_2: D10.2 D13.1 | length 142.5
  BOTTOM w40: D13.1@9525,20003.74 D10.2@9525,20146.26
NETD11_2: D11.2 D12.1 | length 142.5
  BOTTOM w40: D12.1@9325,20003.74 D11.2@9325,20146.26
NETD14_1: D14.1 R324.1 R325.2 R326.1 | length 283.1
  BOTTOM w40: D14.1@23615,18665.53 23530.53,18665.53 R326.1@23525,18660 23525,18564.39 R325.2@23525.15,18564.24 R324.1@23620.15,18564.24
NETD14_2: D14.2 R323.2 T1.1 | length 10020.4
  BOTTOM w40: T1.1@15750,19765.57 15892.91,19908.48 R323.2@15892.91,20025 15892.91,20534.46 16214.54,20856.09 22205.46,20856.09 23695,19366.55 23695,18815 23674.47,18794.47 D14.2@23615,18794.47
NETD15_1: D15.1 R328.1 R329.2 R330.1 | length 279.2
  BOTTOM w20: D15.1@23179.47,18322.15 R329.2@23179.47,18427.15 R330.1@23275,18427.15 R328.1@23353.65,18427.15
NETD15_2: D15.2 R327.2 T2.4 | length 13437.2
  BOTTOM w40: T2.4@15631.89,13880.54 15774.8,13737.63 R327.2@15774.8,13585.28 15774.8,13485.68 16458.33,12802.15 21235.15,12802.15 21820.15,13387.15 23020.15,13387.15 23370.15,13737.15 23370.15,14952.15 23050.53,15271.77 D15.2@23050.53,18322.15
NETD16_2: D16.2 R25.1 | length 80.5
  BOTTOM w12: R25.1@22625,19200 D16.2@22705.53,19200
NETD20_2: D20.2 R14.1 | length 103.9
  BOTTOM w50: R14.1@17557.09,18035 17571.56,18049.47 D20.2@17655,18049.47
NETD21_1: D21.1 Q1.1 R14.2 R15.1 R41.2 | length 595.3
  BOTTOM w50: D21.1@17237.8,18029.47 17238.33,18030 R15.1@17337.8,18030 17342.8,18035 R14.2@17442.91,18035 R41.2@17442.91,17925
  BOTTOM w60: Q1.1@16999.29,18124.63 17094.45,18029.47 D21.1@17237.8,18029.47
NETD23_2: D23.2 R43.1 | length 103.9
  BOTTOM w50: R43.1@17552.09,19405 17566.56,19419.47 D23.2@17650,19419.47
NETD24_1: D24.1 Q2.1 R42.2 R43.2 R44.1 | length 609.9
  BOTTOM w50: D24.1@17237.8,19399.47 17337.27,19399.47 R44.1@17337.8,19400 17342.8,19405 R43.2@17437.91,19405 R42.2@17437.91,19295
  BOTTOM w60: Q2.1@16999.29,19541.96 17141.78,19399.47 D24.1@17237.8,19399.47
NETD25_2: D25.2 R46.1 | length 103.9
  BOTTOM w50: R46.1@17552.09,14838.07 17566.56,14852.54 D25.2@17650,14852.54
NETD26_1: D26.1 Q3.1 R45.2 R46.2 R47.1 | length 609.9
  BOTTOM w50: D26.1@17237.8,14832.54 17238.33,14833.07 R47.1@17337.8,14833.07 17342.8,14838.07 R46.2@17437.91,14838.07 R45.2@17437.91,14728.07
  BOTTOM w60: Q3.1@16999.29,14975.03 17141.78,14832.54 D26.1@17237.8,14832.54
NETD27_2: D27.2 R49.1 | length 103.9
  BOTTOM w50: R49.1@17557.09,13468.07 17571.56,13482.54 D27.2@17655,13482.54
NETD28_1: D28.1 Q4.1 R48.2 R49.2 R50.1 | length 595.3
  BOTTOM w50: D28.1@17237.8,13462.54 17238.33,13463.07 R50.1@17337.8,13463.07 17342.8,13468.07 R49.2@17442.91,13468.07 R48.2@17442.91,13358.07
  BOTTOM w60: Q4.1@16999.29,13557.7 17094.45,13462.54 D28.1@17237.8,13462.54
NETD50_1: D50.1 R54.1 | length 105.5
  BOTTOM w12: D50.1@21907.6,19242.24 21907.6,19316.1 R54.1@21930,19338.5
NETD50_3: D50.3 D51.3 R55.1 U5.1 | length 689.9
  BOTTOM w12: D50.3@21945,19147.76 21945,19155 21968.5,19178.5 R55.1@22070,19178.5 22143.5,19178.5 22165,19200 D51.3@22192.76,19200 22255,19262.24 22255,19435 22235,19455 22205,19455 22170,19490 U5.1@22170,19537.72
NETD65_2: D65.2 R315.2 | length 132.7
  BOTTOM w40: R315.2@14365,14300.82 14375.83,14300.82 14414.47,14262.18 D65.2@14414.47,14195
NETD82_1: D82.1 R377.2 | length 101.9
  BOTTOM w20: R377.2@14835,14375 14892.51,14375 14896.98,14370.53 D82.1@14935,14370.53
NETF1_1: F1.1 K1.4 K1.5 RT1.1 RT2.1
NETF1_2: F1.2 J1.1
NETH2_3: H2.3 R93.2 R95.2
NETH2_4: H2.4 R96.2 R97.2
NETL1_2: L1.2 L4.1
NETL2_1: L2.1 L3.2
NETL3_1: L3.1 L20.2 L21.2 L22.2 L23.2 L28.2 L29.2 L30.2 L31.2
NETL4_2: L4.2 L16.2 L17.2 L18.2 L19.2 L24.2 L25.2 L26.2 L27.2
NETL16_1: L16.1 L17.1 L18.1 L19.1 T1.2
NETL20_1: L20.1 L21.1 L22.1 L23.1 T2.3
NETQ6_1: Q6.1 R385.2 R386.1 | length 194.8
  BOTTOM w12: R385.2@22500,19580 R386.1@22500,19490 22507.6,19482.4 Q6.1@22507.6,19388.31
NETQ6_3: Q6.3 R25.2 R388.1 | length 181.7
  BOTTOM w12: R388.1@22465,19200 R25.2@22545,19200 Q6.3@22545,19301.69
NETQ10_1: Q10.1 Q11.1 R11.2 | length 426.6
  BOTTOM w30: Q10.1@21969.8,18954.05 21989.04,18954.05 22014.99,18980 22205.01,18980 22230.96,18954.05 Q11.1@22244.8,18954.05 22333.86,18954.05 R11.2@22362.91,18925
NETQ10_3: Q10.3 Q11.3 R92.1 | length 397.5
  BOTTOM w30: R92.1@21969.89,18735 21969.8,18735.09 Q10.3@21969.8,18835.95 22029.04,18835.95 22054.99,18810 22200.01,18810 22225.96,18835.95 Q11.3@22244.8,18835.95
NETQ12_1: Q12.1 Q13.1 R16.2 | length 362.5
  BOTTOM w30: Q12.1@22360.95,18419.8 22360.95,18444.04 22335,18469.99 22335,18615.01 22360.95,18640.96 Q13.1@22360.95,18654.8 22360.95,18758.04 R16.2@22362.91,18760
NETQ12_3: Q12.3 Q13.3 R94.1 | length 367.2
  BOTTOM w30: Q13.3@22479.05,18654.8 22479.05,18645.96 22505,18620.01 22505,18469.99 22479.05,18444.04 Q12.3@22479.05,18419.8 22479.05,18405.95 22510,18375 R94.1@22563.11,18375
NETR1_1: R1.1 R2.2 R3.1 R4.2 R5.1 R6.2
NETR30_1: R30.1 R31.2 | length 85.8
  BOTTOM w40: R30.1@23795,17477.09 R31.2@23795,17562.91
NETR31_1: R31.1 R32.2 | length 85.8
  BOTTOM w40: R31.1@23795,17677.09 R32.2@23795,17762.91
NETR32_1: R32.1 R33.2 | length 85.8
  BOTTOM w40: R32.1@23795,17877.09 R33.2@23795,17962.91
NETR51_1: R51.1 R52.2 R54.2 U5.3 | length 276.2
  BOTTOM w12: R54.2@21930,19401.5 R52.2@22000,19401.5 R51.1@22070,19401.5 U5.3@22070,19537.72
NETR53_2: R53.2 RT3.1 U5.2 | length 214.5
  BOTTOM w12: U5.2@22120,19537.72 22120,19460.19 22140,19440.19 RT3.1@22140,19401.5 R53.2@22210,19401.5
NETR60_1: R60.1 R61.2 R62.1 R63.2
NETR64_1: R64.1 R65.2 R66.1 R67.2
NETR68_2: R68.2 R69.2 R70.2 R71.1 R72.1 R73.1
NETR74_2: R74.2 R75.2 R76.2 R77.1 R78.1 R79.1
NETR80_2: R80.2 R81.2 R82.2 R83.1 R84.1 R85.1
NETR86_2: R86.2 R87.2 R88.2 R89.1 R90.1 R91.1
NETR331_2: R331.2 U1.2 | length 182.6
  BOTTOM w12: R331.2@23130,19038.5 23100,19008.5 23100,18934.99 23125.42,18909.57 U1.2@23156.14,18909.57
NETR332_2: R332.2 R333.1 | length 90
  BOTTOM w16: R333.1@23340,19120 R332.2@23430,19120
NETR334_1: R334.1 R335.2 | length 110.8
  BOTTOM w40: R334.1@9525,20557.09 R335.2@9525,20667.91
NETR335_1: R335.1 R350.2 | length 117.9
  BOTTOM w40: R335.1@9525,20782.09 R350.2@9525,20900
NETR337_2: R337.2 R338.1 | length 90
  BOTTOM w30: R338.1@23340,18950 R337.2@23430,18950
NETR339_2: R339.2 U1.6 | length 132.4
  BOTTOM w12: U1.6@23156.14,18807.21 23207.79,18807.21 23220,18795 R339.2@23283.5,18795
NETR340_2: R340.2 U1.7 | length 148.7
  BOTTOM w12: U1.7@23156.14,18781.61 23198.2,18781.61 23249.81,18730 R340.2@23283.5,18730
NETR346_1: R346.1 U1.19 | length 212.6
  BOTTOM w12: R346.1@22796.5,19030 22834.99,19030 22865,18999.99 22865,18939.57 22895,18909.57 U1.19@22923.86,18909.57
NETR346_2: R346.2 R347.2 | length 67
  BOTTOM w12: R347.2@22666.5,19030 R346.2@22733.5,19030
NETR348_1: R348.1 R349.2 | length 67
  BOTTOM w12: R349.2@22666.5,19095 R348.1@22733.5,19095
NETR348_2: R348.2 U1.20 | length 240.4
  BOTTOM w12: R348.2@22796.5,19095 22825,19095 22890,19030 22890,18950 22904.84,18935.16 U1.20@22923.86,18935.16
NETR350_1: R350.1 R351.2 | length 128.7
  BOTTOM w40: R350.1@9639.18,20900 R351.2@9767.91,20900
NETR379_1: R379.1 R380.2 | length 85.8
  BOTTOM w40: R379.1@23945,17477.09 R380.2@23945,17562.91
NETR380_1: R380.1 R381.2 | length 85.8
  BOTTOM w40: R380.1@23945,17677.09 R381.2@23945,17762.91
NETR381_1: R381.1 R382.2 | length 85.8
  BOTTOM w40: R381.1@23945,17877.09 R382.2@23945,17962.91
NETR385_1: R385.1 U4.1 | length 304.6
  BOTTOM w20: R385.1@22580,19580 22685,19475 22685,19425 22742.6,19367.4 U4.1@22767.24,19367.4
PFC_VCC_12: C32.1 D82.2 J3.1 Q6.2 R10.1 R13.1 R51.2 R55.2 R316.2 R324.2 R328.2 R345.1 R386.2 RT3.2 U5.8 | length 16631.8
  TOP w40: v1(15005,14080) v1(15005,14500)
  BOTTOM w20: D82.2@14935,14499.47 15004.47,14499.47 v1(15005,14500) ; R55.2@22070,19241.5 v1(22070,19290) R51.2@22070,19338.5 ; v1(22140,19290) RT3.2@22140,19338.5 ; U5.8@22170,19752.28 v1(22170,19810) ; v1(22535.15,18822.15) 22535.15,18794.85 R345.1@22565,18765 22580.15,18780.15 v1(22580.15,18822.15) ; R386.2@22580,19490 22582.4,19487.6 v1(22582.4,19430) Q6.2@22582.4,19388.31 ; v1(23620.15,18317.15) R324.2@23620.15,18501.24
  BOTTOM w30: v1(21740,19080) 21687.09,19080 R10.1@21675,19092.09 21712.91,19130 v1(21740,19130)
  BOTTOM w50: R316.2@14397.09,14080 v1(15005,14080) 15173.63,14080 15315.15,13938.48 15315.15,13532.15 16260.15,12587.15 21370.15,12587.15 21920.15,13137.15 23120.15,13137.15 23595.15,13612.15 23595.15,15102.15 23416.65,15280.65 v1(23416.65,18322.15) R328.2@23416.65,18427.15
  other v1: 22160,18554.57 22160,18599.57
PGND: C27.2 C28.2 C29.2 C30.2 C31.2 D1.4 D2.4 D21.2 D24.2 D26.2 D28.2 J2.3 L15.2 NT1.1 NT2.1 NT3.1 Q1.3 Q2.3 Q3.3 Q4.3 R15.2 R44.2 R47.2 R50.2 R71.2 R72.2 R73.2 R77.2 R78.2 R79.2 R83.2 R84.2 R85.2 R89.2 R90.2 R91.2 R93.1 R95.1 R96.1 R97.1 | length 968.8
  BOTTOM w20: D28.2@17237.8,13333.6 17237.8,13342.8 17278.07,13383.07 R50.2@17337.8,13383.07 ; D26.2@17237.8,14703.6 17287.27,14753.07 R47.2@17337.8,14753.07 ; D21.2@17237.8,17900.53 17243.81,17900.53 17293.28,17950 R15.2@17337.8,17950 ; D24.2@17237.8,19270.53 17243.81,19270.53 17293.28,19320 R44.2@17337.8,19320 ; v1(17315,13333.07) 17315,13360.27 R50.2@17337.8,13383.07 ; v1(17315,14703.07) 17315,14730 17337.8,14752.8 R47.2@17337.8,14753.07 ; v1(17315,17900) 17315,17927.2 R15.2@17337.8,17950 ; v1(17315,19270) 17315,19297.2 R44.2@17337.8,19320 ; v1(17360,13333.07) 17360,13365 17341.93,13383.07 R50.2@17337.8,13383.07 ; v1(17360,14703.07) 17360,14734.07 17341,14753.07 R47.2@17337.8,14753.07 ; v1(17360,17900) 17360,17930 17340,17950 R15.2@17337.8,17950 ; v1(17360,19270) 17360,19300 17340,19320 R44.2@17337.8,19320
  other v1: 18315,13190 18315,13240 18315,13290 21035,13300 18315,13340 21035,13350 21035,13400 21035,13450 17235,14073.07 17360,14073.07 17485,14073.07 17235,15278.07 17360,15278.07 17485,15278.07 21825,18125 21875,18125 21825,18175 21875,18175 17235,18640 17360,18640 17485,18640 17235,19885 17360,19885 17485,19885
SGND: C32.2 C40.2 C42.2 C43.2 C44.2 C151.2 C152.2 C154.2 C155.2 C156.2 C157.2 C158.2 C159.2 C160.2 C162.2 C164.2 C165.2 C178.2 C179.2 C180.2 C181.2 J3.2 NT1.2 NT2.2 NT3.2 Q5.2 Q7.2 Q11.2 Q11.4 Q13.2 Q13.4 R21.1 R52.1 R53.1 R323.1 R325.1 R327.1 R329.1 R331.1 R332.1 R337.1 R339.1 R340.1 R341.2 R343.1 R344.1 R347.1 R349.1 R378.1 R383.1 R384.1 R387.1 T1.4 T2.1 U1.16 U4.3 U5.4 | length 40540.9
  BOTTOM w15: C181.2@22740,18840 22748.5,18831.5 C164.2@22815,18831.5 22854.5,18831.5 v1(22856,18830) 22858.79,18832.79 U1.16@22923.86,18832.79 v1(22980,18832.79)
  BOTTOM w20: Q7.2@14552.24,14377.6 14639.25,14377.6 14645.15,14383.5 C178.2@14655,14383.5 14731.5,14383.5 R378.1@14740,14375 ; v1(22000,19290) R52.1@22000,19338.5 ; v1(22020,19480) U5.4@22020,19537.72 ; v1(22210,19290) R53.1@22210,19338.5 ; Q5.2@22407.4,19392.24 22407.4,19484.1 C180.2@22401.5,19490 22401.5,19571.5 R387.1@22410,19580 v1(22410,19635) ; v1(22572,18525) R343.1@22618.5,18525 ; v1(22573,18655) R344.1@22618.5,18655 ; R349.1@22603.5,19095 R347.1@22603.5,19030 22603.5,19001.5 v1(22615,18990) ; v1(22630,19330) U4.3@22672.76,19330 ; v1(22705,18460) C160.2@22753.5,18460 ; v1(22705,18590) C162.2@22753.5,18590 ; C165.2@22790,18955 v1(22836,18955) ; C179.2@22920,19370.91 v1(22920,19419.41) ; v1(22988.5,18990) C152.2@22988.5,19035 ; R383.1@23000,19387.91 v1(23000,19435) ; R21.1@23051.5,19230 v1(23095,19230) ; R384.1@23105,19422.09 v1(23105,19475) ; R331.1@23130,19101.5 v1(23130,19150) ; C151.2@23195,19101.5 v1(23195,19150) ; C155.2@23265,18933.5 v1(23265,18982) ; C154.2@23265,19101.5 v1(23265,19150) ; v1(23395,18595) C157.2@23346.5,18595 C156.2@23346.5,18660 v1(23395,18660) ; v1(23395,18730) R340.1@23346.5,18730 R339.1@23346.5,18795 v1(23395,18795) ; v1(23465.15,18432.15) 23507.24,18432.15 R325.1@23525.15,18450.06 23498.06,18477.15 v1(23465.15,18477.15) ; R337.1@23510,18950 v1(23560,18950) ; R332.1@23510,19120 v1(23560,19120)
  BOTTOM w30: v1(21675,18765) C40.2@21675,18815 ; v1(21750,18780) C42.2@21750,18828.5 ; v1(22045,18895) Q11.4@22134.57,18895 Q11.2@22236.93,18895 ; Q13.4@22420,18544.57 Q13.2@22420,18646.93 v1(22420,18710) ; C159.2@23036.5,18635 v1(23036.5,18711.5) ; v1(23090,18715) 23103.5,18701.5 C158.2@23103.5,18635 R341.2@23103.5,18570
  BOTTOM w40: T2.1@16031.89,13880.54 15888.98,13737.63 R327.1@15888.98,13585.28 15888.98,13520.86 16507.69,12902.15 21195.15,12902.15 21805.15,13512.15 22970.15,13512.15 23250.15,13792.15 23250.15,14902.15 22925.15,15227.15 22925.15,18349.3 v1(23003,18427.15) R329.1@23065.29,18427.15 ; T1.4@16150,19765.57 16007.09,19908.48 R323.1@16007.09,20025 16007.09,20089.42 15993,20103.51 15993,20493 16256,20756 22164,20756 23615,19305 v1(23615,18950)
  BOTTOM w50: R378.1@14740,14375 14740,14317 14797,14260 15232.3,14260 15430.15,14062.15 15430.15,13577.15 16310.15,12697.15 21305.15,12697.15 21865.15,13257.15 23065.15,13257.15 23480.15,13672.15 23480.15,15047.15 23290.15,15237.15 v1(23290.15,18322.15)
  other v1: 22140,18309.57 22120,18364.57 21825,18370 21875,18370 22120,18409.57 21825,18420 21875,18420 23035.15,18787.15 23090.15,18787.15 23060.15,18862.15 22988.5,18912.15
SS_V: C165.1 D51.1 Q5.3 U1.18 | length 1039.6
  BOTTOM w12: 22895,18883.98 U1.18@22923.86,18883.98
  BOTTOM w15: C165.1@22710,18955 22710,18940 22744,18906 22859,18906 22881.02,18883.98 22895,18883.98
  BOTTOM w20: Q5.3@22370,19297.76 22370,19275 22332.4,19237.4 D51.1@22287.24,19237.4 22282.4,19237.4 22240,19195 22240,19140 22380,19000 22530,19000 22575,18955 C165.1@22710,18955
VIA_P: C155.1 R338.2 R351.1 U1.5 | length 15953.4
  TOP w40: v1(23615.3,18870) v1(23780,18870)
  BOTTOM w15: U1.5@23156.14,18832.79 23227.29,18832.79
  BOTTOM w20: 23227.29,18832.79 C155.1@23265,18870.5 23339.5,18870.5 R338.2@23340,18870
  BOTTOM w40: R351.1@9882.09,20900 9935.68,20900 9991.9,20956.22 15168.78,20956.22 15400,20725 15793.78,20725 16025,20956.22 22268.78,20956.22 23780,19445 v1(23780,18870) ; R338.2@23340,18870 v1(23615.3,18870)
VREF_P: C159.1 R342.1 U1.13 | length 227.2
  BOTTOM w12: U1.13@22923.86,18756.02 22958.98,18756.02 22973.5,18741.5 C159.1@22973.5,18635 R342.1@22973.5,18570
VS_N: D1.3 D2.3 D13.2 L1.1 L8.1 RV1.1 | length 1950.3
  BOTTOM w30: L1.1@11367.24,19602.76 L1.1@11374.41,19602.76
  BOTTOM w40: D13.2@9525,19846.26 9768.5,19602.76 L1.1@11367.24,19602.76
VS_P: C154.1 R33.1 R333.2 U1.4 | length 1824.9
  TOP w40: v1(23560,19040) v1(23840,19040)
  BOTTOM w15: U1.4@23156.14,18858.39 23193.38,18858.39 23202.49,18867.5
  BOTTOM w20: 23202.49,18867.5 23220,18885.01 23220,18993.5 C154.1@23265,19038.5 23338.5,19038.5 R333.2@23340,19040
  BOTTOM w40: R333.2@23340,19040 v1(23560,19040) ; R33.1@23795,18077.09 23865,18147.09 23865,19015 v1(23840,19040)
pads on no net: D3.MH D4.MH D50.2 D51.2 H2.1 H2.2 J2.2 L1.3 L1.4 L2.3 L2.4 L3.3 L3.4 L4.3 L4.4 L40.3 L40.4 Q1.MH-1 Q2.MH-1 Q3.MH-1 Q4.MH-1 U5.5 U5.6 U5.7
copper on no net: | length 2128.9
  BOTTOM w12: 8655,12665 8655,12715 8685,12745 8735,12745 8765,12715 8765,12665 8735,12635 8685,12635 8655,12665 ; 8655,20820 8655,20870 8685,20900 8735,20900 8765,20870 8765,20820 8735,20790 8685,20790 8655,20820 ; 23820,12750 23820,12800 23850,12830 23900,12830 23930,12800 23930,12750 23900,12720 23850,12720 23820,12750
  BOTTOM w100: 8368.3,12428.96 8402.63,12394.63 8470.11,12327.15 ; 8368.3,21100.46 8402.63,21134.79 8458.69,21190.85 ; 23860.85,21190.85 24174.15,21190.85 24229.4,21135.6 24229.4,21134.79 24230.21,21134.79 24278.85,21086.15 24278.85,20800

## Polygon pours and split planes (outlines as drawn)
NETC82_1 on TOP "TOP-NETC82_1" (solid, pour order 1000): 37 vertices, not listed, extent 15972.5,13700 16890,15745
VS_N on TOP "TOP-VS_N" (solid, pour order 1001): 30 vertices, not listed, extent 11150,17800 14225,19700
SGND on TOP "TOP-SGND" (solid, pour order 1002): 22095,18900 22095,18475 22157.5,18412.5 22157.5,18312.5 22157.5,18299.5 22150.15,18292.15 21680.15,18292.15 21655,18317.3 21655,18335 21655,18385 21655,18950 21690,18985 22075,18985 22095,18965 22095,18900
SGND on TOP "TOP-SGND 1" (solid, pour order 1003): 56 vertices, not listed, extent 21900,18290 23820,20380
PGND on TOP "TOP-PGND" (solid, pour order 1004): 121 vertices, not listed, extent 13675,12702.15 22750,20105
PFC_VCC_12 on TOP "TOP-PFC_VCC_12" (solid, pour order 1005): 57 vertices, not listed, extent 21700,18150 23800,20660
NETL20_1 on TOP "TOP-NETL20_1" (solid, pour order 1006): 15550,14425 15525,14450 15525,15350 15525,15440 15560,15475 15715,15475 15725,15475 15795,15475 15825,15445 15825,14460 15790,14425 15735,14425 15550,14425
NETL16_1 on TOP "TOP-NETL16_1" (solid, pour order 1007): 15750,18425 15500,18425 15450,18475 15450,19200 15475,19225 15800,19225 15825,19200 15825,18500 15750,18425
NETL4_2 on TOP "TOP-NETL4_2" (solid, pour order 1008): 18 vertices, not listed, extent 14225,17575 15300,19700
NETL3_1 on TOP "TOP-NETL3_1" (solid, pour order 1009): 20 vertices, not listed, extent 14225,14600 15375,16475
NETL2_1 on TOP "TOP-NETL2_1" (solid, pour order 1010): 11825,15825 11825,15975 11825,16050 11900,16125 13825,16125 13900,16050 13900,15950 13900,15825 13900,15700 13850,15650 11900,15650 11825,15725 11825,15825
NETL1_2 on TOP "TOP-NETL1_2" (solid, pour order 1011): 18 vertices, not listed, extent 11825,19425 13900,20025
NETF1_2 on TOP "TOP-NETF1_2" (solid, pour order 1012): 13950,12700 13950,12825 13950,12875 14000,12925 14375,12925 14425,12875 14425,12825 14425,12700 14425,12650 14375,12600 14000,12600 13950,12650 13950,12700
NETF1_1 on TOP "TOP-NETF1_1" (solid, pour order 1013): 19 vertices, not listed, extent 13650,12675 15500,13425
NETD1_2 on TOP "TOP-NETD1_2" (solid, pour order 1014): 27 vertices, not listed, extent 11100,15625 14225,17650
NETC85_1 on TOP "TOP-NETC85_1" (solid, pour order 1015): 20 vertices, not listed, extent 15525,15675 17100,16520
NETC84_1 on TOP "TOP-NETC84_1" (solid, pour order 1016): 23 vertices, not listed, extent 15450,17347.5 17100,18300
NETC80_1 on TOP "TOP-NETC80_1" (solid, pour order 1017): 45 vertices, not listed, extent 16075,18235 16895,20285
NETC41_2 on TOP "TOP-NETC41_2" (solid, pour order 1018): 12325,13425 12275,13475 12275,13700 12350,13775 14925,13775 14950,13750 14950,13650 14950,13600 14925,13575 14525,13575 14375,13425 12325,13425
NETC22_1 on TOP "TOP-NETC22_1" (solid, pour order 1019): 17 vertices, not listed, extent 22000.15,12712.15 22370.15,12822.15
NETC18_1 on TOP "TOP-NETC18_1" (solid, pour order 1020): 20 vertices, not listed, extent 8675.15,15375 8881.57,15800
NETC17_1 on TOP "TOP-NETC17_1" (solid, pour order 1021): 8770.15,19242.15 8750.15,19222.15 8750.15,19032.15 8675,18957 8675,18900 8692.85,18882.15 8702.85,18872.15 8770.15,18872.15 8780.15,18882.15 8790.15,18892.15 8865.15,18967.15 8865.15,19217.15 8860.15,19222.15 8840.15,19242.15 8770.15,19242.15
NETC16_1 on TOP "TOP-NETC16_1" (solid, pour order 1022): 18 vertices, not listed, extent 8715.15,12900 8866.15,13250
NETC15_1 on TOP "TOP-NETC15_1" (solid, pour order 1023): 8775.15,14742.15 8750.15,14717.15 8750.15,14502.15 8750.15,14402.15 8775.15,14377.15 8845.15,14377.15 8865.15,14377.15 8890.15,14402.15 8890.15,14707.15 8855.15,14742.15 8850.15,14742.15 8775.15,14742.15
NETC14_2 on TOP "TOP-NETC14_2" (solid, pour order 1024): 24 vertices, not listed, extent 9900,17250 11450,18325
NETC14_1 on TOP "TOP-NETC14_1" (solid, pour order 1025): 23 vertices, not listed, extent 9925,17825 11475,18950
NETC13_2 on TOP "TOP-NETC13_2" (solid, pour order 1026): 24 vertices, not listed, extent 8660,16025 10200,18350
NETC13_1 on TOP "TOP-NETC13_1" (solid, pour order 1027): 27 vertices, not listed, extent 8575,16350 9500,18725
NETC12_2 on TOP "TOP-NETC12_2" (solid, pour order 1028): 20 vertices, not listed, extent 8675,13475 10200,15725
NETC12_1 on TOP "TOP-NETC12_1" (solid, pour order 1029): 9425,15750 9500,15675 9500,15600 9500,14025 9500,13925 9425,13850 9350,13850 9150,13850 9122.3,13850 9048.65,13923.65 9048.65,15673.65 9125,15750 9250,15750 9425,15750
NETC11_2 on TOP "TOP-NETC11_2" (solid, pour order 1030): 21 vertices, not listed, extent 9675,12925 11950,13750
NETC11_1 on TOP "TOP-NETC11_1" (solid, pour order 1031): 24 vertices, not listed, extent 9225,12550 13775,13225
CASE on TOP "TOP-CASE" (solid, pour order 1032): 78 vertices, not listed, extent 8622,12277.15 24042,12377.15
CASE on TOP "TOP-CASE 1" (solid, pour order 1033): 87 vertices, not listed, extent 8315.15,12590.85 8418.3,20897.15
CASE on TOP "TOP-CASE 2" (solid, pour order 1034): 78 vertices, not listed, extent 8662,21140.85 24022,21240.85
CASE on TOP "TOP-CASE 3" (solid, pour order 1035): 78 vertices, not listed, extent 24228.85,12564 24328.85,20934
NETH2_4 on BOTTOM "BOTTOM-NETH2_4" (solid, pour order 1036): 20370,13350 20370,13490 20440,13560 20830,13560 20885,13505 20885,13310 20885,13295 20840,13250 20435,13250 20370,13315 20370,13350
NETH2_3 on BOTTOM "BOTTOM-NETH2_3" (solid, pour order 1037): 18785,13145 18500,13145 18465,13180 18465,13440 18575,13550 18805,13550 18865,13490 18865,13225 18785,13145
HV_DC on BOTTOM "BOTTOM-HV_DC" (solid, pour order 1038): 88 vertices, not listed, extent 13650,14325 22750,17371.2
NETC82_1 on BOTTOM "BOTTOM-NETC82_1" (solid, pour order 1039): 37 vertices, not listed, extent 15972.5,13700 16890,15745
VS_N on BOTTOM "BOTTOM-VS_N" (solid, pour order 1040): 30 vertices, not listed, extent 11150,17800 14225,19700
SGND on BOTTOM "BOTTOM-SGND" (solid, pour order 1041): 21805,18270 21785,18290 21785,18425 21805,18445 21905,18445 21920,18430 21920,18285 21905,18270 21902,18267 21808,18267 21805,18270
SGND on BOTTOM "BOTTOM-SGND 1" (solid, pour order 1042): 22195,18419.57 22195,18344.57 22205,18334.57 22205,18289.57 22200,18284.57 22120,18284.57 22105,18299.57 22105,18419.57 22110,18424.57 22190,18424.57 22195,18419.57
SGND on BOTTOM "BOTTOM-SGND 2" (solid, pour order 1043): 20 vertices, not listed, extent 21445.15,18712.15 22030.15,19587.15
SGND on BOTTOM "BOTTOM-SGND 3" (solid, pour order 1044): 52 vertices, not listed, extent 22970,18700 23115,19000
PGND on BOTTOM "BOTTOM-PGND" (solid, pour order 1045): 21060,13280 20975,13280 20965,13290 20965,13455 20980,13470 21055,13470 21070,13455 21070,13290 21060,13280
PGND on BOTTOM "BOTTOM-PGND 1" (solid, pour order 1046): 21785,18110 21785,18230 21805,18250 21808,18253 21897,18253 21900,18250 21920,18230 21920,18110 21900,18090 21805,18090 21785,18110
PGND on BOTTOM "BOTTOM-PGND 2" (solid, pour order 1047): 18375,13170 18290,13170 18280,13180 18280,13350 18285,13355 18375,13355 18385,13345 18385,13180 18375,13170
PGND on BOTTOM "BOTTOM-PGND 3" (solid, pour order 1048): 16980,19910 16945,19945 16945,19990 16975,20020 17025,20020 17075,19970 17515,19970 17520,19965 17520,19825 17510,19815 17120,19815 17075,19815 16980,19910
PGND on BOTTOM "BOTTOM-PGND 4" (solid, pour order 1049): 17535,18570 17115,18570 17055,18510 16975,18510 16955,18530 16955,18595 17075,18715 17540,18715 17550,18705 17550,18585 17535,18570
PGND on BOTTOM "BOTTOM-PGND 5" (solid, pour order 1050): 17 vertices, not listed, extent 16945,15208.07 17520,15450
PGND on BOTTOM "BOTTOM-PGND 6" (solid, pour order 1051): 17535,14003.07 17115,14003.07 17055,13943.07 16975,13943.07 16955,13963.07 16955,14028.07 17075,14148.07 17540,14148.07 17550,14138.07 17550,14018.07 17535,14003.07
PFC_VCC_12 on BOTTOM "BOTTOM-PFC_VCC_12" (solid, pour order 1052): 22175,18614.57 22175,18454.57 22170,18449.57 22110,18449.57 22105,18454.57 22105,18614.57 22110,18619.57 22170,18619.57 22175,18614.57
NETR86_2 on BOTTOM "BOTTOM-NETR86_2" (solid, pour order 1053): 17535,20035 17205,20035 17190,20050 17190,20180 17195,20185 17535,20185 17545,20175 17545,20045 17535,20035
